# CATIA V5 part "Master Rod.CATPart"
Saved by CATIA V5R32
Part number: Master Rod
Bounding box of the stored display mesh (mm): x -55.99 to 55.99, y -51.999 to 267.322, z -35 to 35
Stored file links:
  D:\PROJECTS\Project 2022\CATIA V5 6R 2022\Resources\Part Files\c13_catia_v5_6r2022_prt\c13_catia_v5-6r2022_figr_13-41\Part & Asm files\Master Rod.CATPart
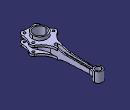
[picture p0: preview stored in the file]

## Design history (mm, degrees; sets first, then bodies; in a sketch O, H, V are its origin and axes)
Body1 (main body)
  Sketch1 on xy-plane, origin (0, 0, 0), H (1, 0, 0), V (0, 1, 0)
    arc A1 centre (0, 0) radius 31.5 from (-26.3425, 17.272) to (26.3425, 17.272) ccw
    arc A2 centre (0, 250) radius 17.5 from (14.7398, 240.5666) to (-14.7398, 240.5666) ccw
    point P1 (0, 250)
    line L1 (9, 220) -> (13, 60)
    point P2 (9, 220)
    point P3 (13, 60)
    arc A3 centre (94.6219, 62.0405) radius 81.6474 from (13, 60) to (26.3425, 17.272) ccw
    point P5 (26.3425, 17.272)
    arc A4 centre (45.4514, 220.9113) radius 36.4628 from (9, 220) to (14.7398, 240.5666) cw
    point P7 (14.7398, 240.5666)
    point P8 (-14.7398, 240.5666)
    point P9 (-9, 220)
    arc A5 centre (-45.4514, 220.9113) radius 36.4628 from (-9, 220) to (-14.7398, 240.5666) ccw
    point P11 (-13, 60)
    line L2 (-9, 220) -> (-13, 60)
    point P12 (-26.3425, 17.272)
    arc A6 centre (-94.6219, 62.0405) radius 81.6474 from (-13, 60) to (-26.3425, 17.272) cw
    radius A1 = 31.5
    radius A2 = 17.5
    distance P1 H = 250
    distance V P3 = 13
    distance P2 V = 9
    distance P1 P2 V = 30
    distance P3 P2 V = 160
    coincidence: P1 V
    tangency: A3 L1, A3 A1, A4 L1, A4 A2
    symmetry: P7 P8 V, P2 P9 V, A4 A5 V, P3 P11 V, L1 L2 V, P5 P12 V, A3 A6 V
  Pad1: profile Sketch1, direction (0, 0, 1), length 21, mirrored extent
  Sketch2 on face of Pad1, origin (0, 0, 21), H (1, 0, 0), V (0, 1, 0)
    point P1 (43, 16)
    point P2 (26, -39)
    arc A1 centre (43, 16) radius 13 from (53.3864, 8.1819) to (49.3111, 27.3653) ccw
    arc A2 centre (26, -39) radius 13 from (22.0235, -51.3769) to (38.9864, -38.4063) ccw
    reference projected line E1 (9, 220) -> (12.2872, 88.5122) from edge of Pad1
    arc A3 centre (84.2647, 90.3117) radius 72 from (49.3111, 27.3653) to (12.2872, 88.5122) cw
    point P5 (49.3111, 27.3653)
    point P6 (12.2872, 88.5122)
    arc A4 centre (110.9113, -35.118) radius 72 from (38.9864, -38.4063) to (53.3864, 8.1819) cw
    point P8 (38.9864, -38.4063)
    point P9 (53.3864, 8.1819)
    point P10 (-12.2872, 88.5122)
    point P11 (-49.3111, 27.3653)
    arc A5 centre (-84.2647, 90.3117) radius 72 from (-49.3111, 27.3653) to (-12.2872, 88.5122) ccw
    point P13 (-53.3864, 8.1819)
    arc A6 centre (-43, 16) radius 13 from (-53.3864, 8.1819) to (-49.3111, 27.3653) cw
    point P15 (-38.9864, -38.4063)
    arc A7 centre (-110.9113, -35.118) radius 72 from (-38.9864, -38.4063) to (-53.3864, 8.1819) ccw
    arc A8 centre (-26, -39) radius 13 from (-22.0235, -51.3769) to (-38.9864, -38.4063) cw
    line L1 (12.2872, 88.5122) -> (-12.2872, 88.5122)
    arc A9 centre (0, -119.9259) radius 72 from (-22.0235, -51.3769) to (22.0235, -51.3769) cw
    distance V P2 = 26
    distance P2 P1 H = 17
    distance P1 P2 V = 55
    distance P2 H = 39
    radius A1 = 13
    radius A2 = 13
    radius A3 = 72
    radius A4 = 72
    radius A9 = 72
    tangency: A3 E1, A3 A1, A4 A1, A4 A2, A9 A8, A9 A2
    symmetry: P6 P10 V, P5 P11 V, A3 A5 V, P9 P13 V, A1 A6 V, P8 P15 V, A4 A7 V, A2 A8 V
    horizontal: L1 H
  Pad2: profile Sketch2, direction (0, 0, -1), length 9
  Mirror1: of Pad2, Sketch2, about xy-plane
  Sketch3 on xy-plane, origin (0, 0, 0), H (1, 0, 0), V (0, 1, 0)
    circle A1 centre (0, 0) radius 31.5
    reference projected arc E1 centre (0, 0) radius 31.5 from (-26.3425, 17.272) to (26.3425, 17.272) ccw from edge of Pad2
    tangency: A1 E1
  Pad3: profile Sketch3, direction (0, 0, 1), length 35, mirrored extent
  Sketch4 on xy-plane, origin (0, 0, 0), H (1, 0, 0), V (0, 1, 0)
    circle A1 centre (0, 0) radius 26
    circle A2 centre (43, 16) radius 5
    circle A3 centre (26, -39) radius 5
    reference projected arc E1 centre (43, 16) radius 13 from (53.3864, 8.1819) to (49.3111, 27.3653) ccw from edge of Pad2
    reference projected arc E2 centre (26, -39) radius 13 from (22.0235, -51.3769) to (38.9864, -38.4063) ccw from edge of Pad2
    circle A4 centre (-26, -39) radius 5
    circle A5 centre (-43, 16) radius 5
    radius A1 = 26
    radius A3 = 5
    radius A2 = 5
    concentricity: A2 E1, A3 E2
    symmetry: A3 A4 V, A2 A5 V
  Pocket1: profile Sketch4, direction (0, 0, -1), length 35, mirrored extent
  Sketch5 on yz-plane, origin (0, 0, 0), H (0, 1, 0), V (0, 0, 1)
    line L1 (123.0834, 12) -> (250, 9)
    point P1 (123.0834, 12)
    point P2 (250, 9)
    arc A1 centre (124.9266, 89.9782) radius 78 from (88.5122, 21) to (123.0834, 12) ccw
    line L2 (88.5122, 21) -> (88.5122, 33.8539)
    line L3 (88.5122, 33.8539) -> (280.7471, 33.8539)
    line L4 (280.7471, 33.8539) -> (280.7471, 8.2732)
    point P8 (280.7471, 8.2732)
    line L5 (280.7471, 8.2732) -> (250, 9)
    distance P1 H = 12
    distance H P2 = 9
    distance V P2 = 250
    radius A1 = 78
    tangency: A1 L1, L5 A1
    vertical: L2 V, L4 V
    horizontal: L3 H
    coincidence: P8 L1
  Pocket2: profile Sketch5, direction (-1, 0, 0), length 35, mirrored extent
  Mirror2: of Pocket2, Sketch5, about xy-plane
  Sketch6 on xy-plane, origin (0, 0, 0), H (1, 0, 0), V (0, 1, 0)
    circle A1 centre (0, 250) radius 17.5
    point P1 (0, 250)
    reference projected arc E1 centre (0, 250) radius 17.5 from (17.5, 250) to (-17.5, 250) ccw from edge of Mirror2
    reference projected arc E2 centre (0, 250) radius 17.5 from (17.5, 250) to (-17.5, 250) ccw from edge of Mirror2
    coincidence: P1 V
    concentricity: E1 A1
    tangency: E2 A1
  Pad4: profile Sketch6, direction (0, 0, 1), length 21, mirrored extent
  Sketch7 on xy-plane, origin (0, 0, 0), H (1, 0, 0), V (0, 1, 0)
    circle A1 centre (0, 250) radius 12
    point P1 (0, 250)
    reference projected circle E1 centre (0, 250) radius 17.5 from edge of Pad4
    radius A1 = 12
    coincidence: P1 V
    concentricity: A1 E1
  Pocket3: profile Sketch7, direction (0, 0, -1), length 21, mirrored extent
  Sketch8 on xy-plane, origin (0, 0, 0), H (1, 0, 0), V (0, 1, 0)
    construction line L1 (0, 70) -> (0, 220)
    point P1 (0, 70)
    point P2 (0, 220)
    line L2 (-6, 70) -> (-6, 220)
    line L3 (6, 220) -> (6, 70)
    arc A1 centre (0, 220) radius 6 from (-6, 220) to (6, 220) cw
    arc A2 centre (0, 70) radius 6 from (6, 70) to (-6, 70) cw
    point P7 (0, 250)
    reference projected circle E1 centre (0, 250) radius 12 from edge of Pocket3
    length L1 = 150
    distance P7 P2 = 30
    radius A1 = 6
    coincidence: P1 V, P7 L1
    vertical: L1 V
    tangency: A1 L2, A2 L2, A1 L3, A2 L3
    parallelism: L1 L2
    concentricity: P7 E1
  Pocket4: profile Sketch8, direction (0, 0, 1), through (limit type 6), opposite side length -2.5
  Mirror3: of Pocket4, Sketch8, about xy-plane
